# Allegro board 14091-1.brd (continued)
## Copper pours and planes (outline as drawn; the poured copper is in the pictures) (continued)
0D95V_VGA_S0 on TOP: 81.44,103.25 81.31,103.38 81.31,103.63 81.19,103.76 79.54,103.76 79.28,104.01 79.28,104.65 79.03,104.9 78.65,104.9 78.52,105.03 78.52,107.7 78.65,107.82 79.28,107.82 79.66,107.44 79.66,106.55 79.92,106.3 80.68,106.3 80.81,106.17 80.81,104.9 80.93,104.78 84.62,104.78 84.74,104.65 84.74,104.01 84.62,103.89 84.11,103.89 83.47,103.25 83.22,103.25 82.71,103.76 81.95,103.76 81.82,103.63 81.82,103.38 81.69,103.25
0D95V_VGA_S0 on TOP: 100.62,103.25 99.98,103.89 99.98,106.55 100.24,106.81 102.27,106.81 102.4,106.68 102.4,103.38 102.27,103.25
0D95V_VGA_S0 on BOTTOM: 81.59,103.1 81.46,103.23 81.46,103.74 81.34,103.87 80.57,103.87 80.19,104.25 80.19,106.41 80.07,106.53 79.3,106.53 78.92,106.91 78.92,107.29 79.56,107.93 80.45,107.93 80.57,107.8 80.57,107.17 80.7,107.04 81.08,107.04 81.21,106.91 81.21,105.52 81.59,105.14 84.56,105.14 84.69,105.26 85.12,105.26 86.67,106.81 87.92,106.81 88.68,106.05 100.62,106.05 100.74,105.92 100.74,104.25 100.49,103.99 89.72,103.99 89.23,103.5 87.41,103.5 87.13,103.23 84.38,103.23 84.26,103.36 82.48,103.36 82.23,103.1 ; 8 cut-outs
1D0V_S5 on TOP: 37.75,138.68 37.75,140.46 39.02,140.46 39.15,140.59 39.15,141.6 40.29,142.75 40.29,143.13 40.8,143.64 41.82,143.64 41.94,143.51 43.26,143.51 45.5,145.75 45.5,155.7 45.75,155.96 49.82,155.96 50.45,155.32 50.45,153.92 50.58,153.8 57.92,153.8 59.47,152.25 59.47,141.73 59.34,141.6 57.44,141.6 57.31,141.73 57.31,141.86 57.18,141.99 55.28,141.99 55.15,141.86 55.15,141.35 54.9,141.1 53.75,141.1 53.63,141.22 53.63,141.6 53.37,141.86 52.23,141.86 50.96,140.59 48.42,140.59 48.29,140.72 48.29,142.24 48.42,142.37 49.82,142.37 49.82,144.4 49.56,144.65 48.17,144.65 46.77,143.26 46.77,141.73 46.64,141.6 41.69,141.6 40.93,140.84 40.93,138.81 40.8,138.68 ; 6 cut-outs
1D8V_S0 on BOTTOM: 81.31,196.98 81.06,197.23 81.06,197.61 80.68,197.99 79.54,197.99 79.28,198.25 79.28,199.14 79.41,199.26 82.71,199.26 82.84,199.14 82.84,198.75 83.85,197.74 83.85,197.1 83.73,196.98 ; 4 cut-outs
1D8V_S5 on TOP: 91.73,124.33 91.47,124.59 91.47,126.49 91.6,126.62 93,126.62 93.38,126.24 95.16,126.24 95.28,126.36 95.28,127.38 95.08,127.58 93.99,127.58 93.96,127.61 93.96,128.09 94.01,128.14 95.46,128.14 95.56,128.04 95.56,127.84 95.77,127.64 97.06,127.64 97.19,127.51 97.19,125.6 97.06,125.48 96.68,125.48 96.43,125.22 96.43,124.46 96.3,124.33 ; 5 cut-outs
1D8V_S5 on BOTTOM: 81.44,199.52 81.31,199.64 81.31,201.29 81.57,201.55 84.87,201.55 85.12,201.29 85.12,199.64 85,199.52
1D8V_VGA_S0 on TOP: 97.44,66.17 97.06,66.55 94.52,66.55 94.27,66.8 94.27,72.01 98.08,75.82 98.08,82.8 98.46,83.19 100.24,83.19 101,82.42 101,77.72 101.38,77.34 101.38,69.85 101.25,69.72 99.86,69.72 99.86,70.48 99.22,71.12 97.44,71.12 97.19,70.87 97.19,67.18 97.44,66.93 98.97,66.93 99.09,66.8 99.09,66.17
1D8V_VGA_S0 on TOP: 93.67,109.77 93.56,109.88 93.56,110.29 93.62,110.34 94.04,110.34 95.76,112.07 95.76,112.08 96.04,112.36 96.06,112.36 96.96,113.26 96.96,115.7 97.08,115.82 97.85,115.82 97.97,115.7 97.97,112.12 97.85,111.99 97.08,111.99 96.83,111.74 96.73,111.74 94.76,109.77 ; 3 cut-outs
1D35V_S3 on TOP: 156.37,150.88 155.86,151.38 155.86,166.12 156.12,166.37 158.53,166.37 158.78,166.62 158.78,167.26 158.91,167.39 159.42,167.39 159.42,151.51 158.78,150.88 ; 9 cut-outs
1D35V_S3 on TOP: 90.84,204.09 90.71,204.22 90.71,208.91 90.84,209.04 92.62,209.04 92.74,209.17 92.74,211.2 93.25,211.71 102.14,211.71 103.28,210.57 103.28,208.15 103.54,207.9 103.54,205.87 102.9,205.23 93,205.23 91.85,204.09 ; 1 cut-out
1D35V_S3 on TOP: 140.75,152.02 140.62,152.15 140.62,166.24 140.88,166.5 144.69,166.5 144.94,166.24 144.94,152.4 144.56,152.02 143.16,152.02 143.04,152.15 143.04,152.65 142.78,152.91 141.77,152.91 141.51,152.65 141.51,152.15 141.38,152.02
1D35V_S3 on TOP: 127.92,151.38 127.67,151.64 127.67,168.53 127.92,168.78 129.95,168.78 130.08,168.66 130.08,168.15 129.83,167.89 129.83,151.64 129.57,151.38
1D35V_S3 on BOTTOM: outline of 92 points within 90.33,150.88 159.16,211.71 ; 97 cut-outs
1D35V_VGA_S0 on TOP: 91.73,66.04 90.08,67.69 81.95,67.69 81.44,68.2 81.44,71.88 81.38,71.95 81.38,73.34 78.14,76.58 76.49,76.58 75.47,77.6 75.47,80.01 75.73,80.26 79.15,80.26 83.22,76.2 85,76.2 85.12,76.07 85.12,74.3 85.38,74.04 85.38,71.12 85.5,70.99 89.06,70.99 89.19,70.87 90.97,70.87 91.09,70.74 91.09,69.34 92.24,68.2 93.89,68.2 94.01,68.07 94.01,66.17 93.89,66.04 ; 5 cut-outs
1D35V_VGA_S0 on TOP: 49.16,96.29 49.06,96.39 49.06,97.16 49.18,97.28 50.58,97.28 50.83,97.54 50.83,98.42 49.82,99.44 48.55,99.44 48.42,99.57 48.42,101.09 48.8,101.47 48.8,107.31 48.7,107.42 48.7,108.06 48.79,108.15 50.22,108.15 50.37,108 50.37,105.8 50.94,105.22 50.94,103.41 50.78,103.24 50.77,103.24 50.36,102.84 50.36,102.02 49.82,101.47 49.82,100.84 50.2,100.46 52.23,100.46 52.71,99.98 52.71,96.74 52.25,96.29 ; 11 cut-outs
1D35V_VGA_S0 on TOP: 48.9,114.17 48.59,114.47 48.59,118.36 49.23,119 52.48,119 52.74,118.75 52.74,118.49 52.48,118.24 52.48,117.35 52.61,117.22 53.12,117.22 53.37,116.97 53.37,116.71 53.12,116.46 53.12,115.7 53.39,115.43 53.39,115.3 52.76,114.68 50.88,114.68 50.37,114.17 ; 6 cut-outs
1D35V_VGA_S0 on BOTTOM: 48.65,113.16 48.57,113.23 48.57,118.34 48.84,118.61 50.42,118.61 50.55,118.49 50.55,113.46 50.25,113.16 ; 5 cut-outs
1D35V_VGA_S0 on BOTTOM: 60.51,89.26 60.51,91.29 61.78,92.56 61.78,96.88 61.91,97.01 62.29,97.01 62.54,97.26 62.54,99.29 61.52,100.31 61.52,103.48 58.73,106.28 58.73,108.18 58.86,108.31 59.24,108.31 61.4,106.15 61.4,106.02 62.92,104.5 63.56,104.5 64.19,103.87 64.19,103.1 65.08,102.21 66.48,102.21 67.49,101.2 71.94,101.2 72.19,101.45 72.19,103.76 72.6,104.17 76.05,104.17 76.51,104.63 76.51,105.9 76.64,106.02 77.91,106.02 78.16,106.28 78.92,106.28 79.05,106.15 79.05,103.99 78.67,103.61 78.67,97.39 78.8,97.26 78.8,93.71 78.42,93.32 77.78,93.32 77.02,92.56 72.95,92.56 71.56,93.96 65.72,93.96 61.02,89.26 ; 14 cut-outs
1D35V_VGA_S0 on BOTTOM: 48.55,82.3 48.42,82.42 48.42,86.36 48.59,86.53 48.59,90.04 48.95,90.4 48.95,90.82 49.13,91 50.22,91 50.37,91.16 52.17,91.16 52.66,90.67 52.66,89.55 52.17,89.07 51.64,89.07 51.46,88.89 51.46,88.21 51.87,87.8 52.48,87.8 52.86,88.18 53.29,88.18 53.44,88.03 53.44,86.38 53.29,86.23 53.09,86.23 52.58,86.74 51.92,86.74 51.64,86.46 51.64,85.85 51.87,85.62 52.12,85.62 52.3,85.8 52.66,85.8 52.73,85.72 52.73,84.6 52.75,84.59 52.75,83.07 51.98,82.3 ; 9 cut-outs
1D35V_VGA_S0 on BOTTOM: 52,94.97 50.57,96.39 48.77,96.39 48.59,96.57 48.59,99.23 48.77,99.41 50.5,99.41 50.68,99.59 50.68,100.12 48.85,101.95 48.85,105.86 49.05,106.06 50.8,106.06 51.18,105.68 51.18,101.65 52.61,100.22 52.61,95.17 52.4,94.97 ; 1 cut-out
1D35V_VGA_S0 on L3: 48.04,99.31 48.17,99.44 48.17,118.62 48.8,119.25 52.99,119.25 53.25,119 53.25,115.57 52.23,114.55 52.23,112.14 52.1,112.01 51.47,112.01 50.83,112.65 50.33,112.65 49.94,112.27 49.94,108.46 50.33,108.08 50.96,108.08 51.34,108.46 51.72,108.46 51.85,108.33 51.85,107.31 52.1,107.06 52.1,106.68 51.21,105.79 51.21,102.36 51.98,101.6 51.98,96.9 50.58,95.5 50.58,95.12 49.94,94.49 49.94,91.57 50.33,91.19 50.96,91.19 51.21,90.93 51.21,90.04 51.47,89.79 51.49,89.79 52.38,88.9 52.38,88.23 52.89,87.73 52.89,85.31 53.39,84.81 55.55,84.81 57.08,86.33 57.71,86.33 58.35,85.69 58.35,84.43 57.7,83.79 52.52,83.79 52.48,83.82 51.85,83.82 48.04,87.63
1D35V_VGA_S0 on L4: 52.68,123.38 65.76,123.38 69.12,120.02 71.28,120.02 74.71,116.59 76.11,116.59 79.43,113.26 79.43,106.41 79.43,106.4 79.43,101.98 79.41,101.96 79.41,98.68 84.62,93.47 84.62,92.08 86.14,90.55 86.14,90.42 86.16,90.4 86.16,89.05 86.14,89.03 86.14,83.69 86.01,83.57 80.3,83.57 78.49,81.76 78.49,78.97 78.27,78.74 75.52,78.74 75.14,79.12 75.14,79.58 74.28,80.44 70.34,80.44 69.5,81.28 53.25,81.28 47.88,86.65 47.88,118.58 ; 1 cut-out
3D3V_RUN_FFS on TOP: 82.96,63.88 82.84,64.01 82.84,66.8 83.09,67.06 83.6,67.06 83.85,66.8 83.85,65.91 84.11,65.66 85.12,65.66 85.12,64.77 84.62,64.77 83.73,63.88 ; 2 cut-outs
62883AGND on TOP: 128.3,98.55 128.3,102.11 131.86,102.11 131.86,98.55
62883AGND on BOTTOM: 128.3,98.55 128.3,100.84 128.18,100.97 128.05,100.97 127.92,101.09 127.92,102.49 128.05,102.62 131.48,102.62 131.99,103.12 133.13,103.12 133.26,103 133.26,102.62 133.13,102.49 132.37,102.49 132.11,102.23 132.11,98.81 131.86,98.55 ; 6 cut-outs
AD+_TO_SYS on TOP: 63.91,38.35 63.79,38.48 63.79,40.89 63.41,41.27 62.64,41.27 62.39,41.53 62.39,42.67 71.15,42.67 71.41,42.42 71.41,38.35
AD+_TO_SYS on BOTTOM: 67.47,38.35 66.84,38.99 61.37,38.99 61.37,42.29 61.76,42.67 71.15,42.67 71.41,42.42 71.41,38.35
AD_JK on TOP: 59.6,23.5 57.44,25.65 56.17,25.65 55.79,25.27 54.26,25.27 53.5,26.04 53.5,27.81 53.88,28.19 54.9,28.19 55.53,28.83 55.53,30.1 56.68,31.24 56.68,38.73 56.8,38.86 61.5,38.86 62.01,38.35 62.01,31.37 62.52,30.86 68.61,30.86 68.74,30.73 68.74,28.83 68.61,28.7 66.07,28.7 65.82,28.45 65.82,26.67 64.68,25.53 64.68,23.88 64.3,23.5 ; 2 cut-outs
AD_JK on BOTTOM: 60.23,22.86 57.44,25.65 56.17,25.65 55.79,25.27 54.26,25.27 53.5,26.04 53.5,27.81 53.88,28.19 54.9,28.19 55.53,28.83 55.53,30.1 56.8,31.37 68.11,31.37 68.36,31.11 68.36,28.45 67.6,27.69 66.71,27.69 64.17,25.15 64.17,23.11 63.91,22.86 ; 4 cut-outs
AD_JK on L3: 55.79,25.27 56.17,25.65 57.44,25.65 58.83,24.26 60.36,24.26 64.8,28.7 68.61,28.7 68.74,28.83 68.74,30.61 68.49,30.86 62.64,30.86 62.26,30.48 57.18,30.48 54.9,28.19 53.88,28.19 53.5,27.81 53.5,26.04 54.26,25.27
BT+ on TOP: 39.02,66.04 39.02,67.31 38.9,67.44 30.77,67.44 30.64,67.56 30.64,74.3 30.89,74.55 33.43,74.55 33.56,74.42 33.56,72.9 33.94,72.52 42.71,72.52 43.09,72.14 43.09,66.17 42.96,66.04 ; 5 cut-outs
CAGND on TOP: 38.72,23.16 38.64,23.24 38.64,24.77 38.51,24.89 34.83,24.89 34.7,25.02 34.7,26.67 33.94,27.43 33.94,28.07 34.2,28.32 37.5,28.32 38.01,28.83 39.02,28.83 39.28,28.57 39.28,23.24 39.2,23.16 ; 10 cut-outs
CHG_AGND on TOP: 40.42,43.18 40.17,43.43 40.17,45.09 40.29,45.21 40.8,45.21 40.93,45.09 40.93,44.32 41.31,43.94 43.21,43.94 43.85,44.58 43.85,46.61 45.75,46.61 45.88,46.74 45.88,47.12 46.01,47.24 46.64,47.24 46.77,47.12 46.77,43.69 46.64,43.56 43.21,43.56 42.83,43.18 ; 8 cut-outs
DC_19V on TOP: 62.64,31.75 62.39,32 62.39,36.96 63.03,37.59 71.28,37.59 71.41,37.47 71.41,36.45 71.28,36.32 69.88,36.32 69.5,35.94 69.5,31.88 69.38,31.75 ; 4 cut-outs
DC_19V on BOTTOM: 62.77,34.29 62.39,34.67 62.39,35.18 61.37,36.2 61.37,38.23 66.58,38.23 67.22,37.59 71.03,37.59 71.28,37.34 71.28,35.05 70.52,34.29
DCBATOUT on TOP: 20.1,165.61 19.97,165.74 19.97,172.09 20.23,172.34 26.83,172.34 27.34,171.83 27.34,165.86 27.08,165.61
DCBATOUT on TOP: 40.04,72.9 39.78,73.15 39.78,74.93 39.53,75.18 39.53,75.69 39.28,75.95 39.28,76.83 39.53,77.09 41.94,77.09 43.09,75.95 43.09,73.03 42.96,72.9
DCBATOUT on TOP: 106.71,61.85 106.21,62.36 106.21,67.31 106.59,67.69 121.95,67.69 122.59,68.33 123.6,68.33 126.4,71.12 126.4,74.68 126.78,75.06 126.78,83.06 132.24,83.06 132.43,82.87 132.43,81.85 132.62,81.66 138.08,81.66 138.08,78.36 137.83,78.11 136.94,78.11 136.56,77.72 136.56,75.06 133.76,72.26 133.38,72.26 132.88,71.75 132.88,71.37 126.46,64.96 125.83,64.96 124.11,63.25 112.43,63.25 111.03,61.85
DCBATOUT on TOP: 67.22,43.05 66.96,43.31 61.76,43.31 61.63,43.43 61.63,44.45 61.12,44.96 51.98,44.96 46.9,50.04 41.31,50.04 41.18,50.16 41.18,54.23 41.31,54.36 49.69,54.36 54.01,50.04 63.28,50.04 65.06,48.26 74.33,48.26 74.84,48.77 74.84,49.4 74.96,49.53 75.22,49.53 75.34,49.4 75.34,48.9 75.73,48.51 94.39,48.51 94.71,48.2 97.38,48.2 98.46,47.12 98.46,45.85 96.11,43.5 85.19,43.5 84.87,43.81 72.68,43.81 71.92,43.05
DCBATOUT on TOP: 34.32,79.12 33.94,79.5 33.94,81.92 29.88,85.98 29.88,132.46 27.97,134.37 16.04,134.37 15.78,134.62 15.78,138.56 16.04,138.81 24.67,138.81 25.31,139.45 25.31,140.84 25.5,141.03 32.74,141.03 33.12,140.65 33.12,136.59 35.09,134.62 35.09,89.41 39.28,85.22 39.28,79.38 39.02,79.12 ; 4 cut-outs
DCBATOUT on TOP: 150.78,45.09 150.66,45.21 150.66,47.12 150.78,47.24 151.67,47.24 151.8,47.12 151.8,45.34 151.54,45.09
DCBATOUT on TOP: 46.01,37.08 45.88,37.21 45.88,40.39 46.01,40.51 47.02,40.51 47.28,40.77 52.74,40.77 52.99,40.51 52.99,39.5 52.87,39.37 49.18,39.37 48.93,39.12 48.93,38.61 48.8,38.48 47.91,38.48 47.53,38.1 47.53,37.21 47.4,37.08 ; 1 cut-out
DCBATOUT on BOTTOM: 127.03,75.44 126.78,75.69 126.78,83.06 132.24,83.06 132.37,82.93 132.37,81.92 132.62,81.66 138.08,81.66 138.08,78.36 137.83,78.11 136.94,78.11 136.56,77.72 136.56,75.56 136.43,75.44 ; 2 cut-outs
DCBATOUT on BOTTOM: 14.64,136.14 14,136.78 14,149.48 12.99,150.5 12.99,168.91 14.77,170.69 14.77,186.82 14.38,187.2 14.38,201.8 14.77,202.18 14.77,206.38 15.02,206.63 15.02,211.23 17.31,213.51 17.31,218.57 20.48,221.74 33.69,221.74 35.47,223.52 56.04,223.52 56.55,223.01 59.98,223.01 60.23,222.76 60.23,221.23 60.1,221.11 55.41,221.11 55.02,221.49 36.48,221.49 34.7,219.71 21.62,219.71 19.46,217.55 19.46,216.41 20.1,215.77 25.18,215.77 25.69,216.28 26.96,216.28 27.21,216.53 34.96,216.53 35.21,216.28 35.21,213.23 35.09,213.11 33.94,213.11 32.93,214.12 26.07,214.12 25.56,213.61 21.14,213.61 17.57,210.05 17.57,209.64 17.56,209.63 17.56,188.85 18.07,188.34 25.69,188.34 28.1,190.75 33.18,190.75 34.45,192.02 45.88,192.02 46.01,191.9 46.01,189.74 45.75,189.48 41.69,189.48 39.15,186.94 28.48,186.94 26.7,185.17 18.7,185.17 18.45,184.91 18.45,172.85 18.96,172.34 26.83,172.34 27.34,171.83 27.34,165.86 27.08,165.61 21.37,165.61 19.59,163.83 19.59,136.27 19.46,136.14
DCBATOUT on BOTTOM: 78.14,218.95 77.5,219.58 77.5,223.9 78.01,224.41 81.69,224.41 81.82,224.28 81.82,219.2 81.57,218.95
DCBATOUT on BOTTOM: 63.66,45.09 62.39,46.35 57.44,46.35 56.42,47.37 52.74,47.37 48.67,51.44 45.25,51.44 44.86,51.05 44.86,50.29 44.48,49.91 41.31,49.91 41.18,50.04 41.18,56.26 41.31,56.39 44.99,56.39 45.25,56.64 45.25,72.14 44.36,73.03 40.04,73.03 39.78,73.28 39.78,74.93 39.53,75.18 39.53,75.56 39.09,76.01 39.02,76.01 35.21,79.82 35.21,81.79 35.47,82.04 43.21,82.04 50.58,74.68 50.58,53.09 54.33,49.34 56.99,49.34 58.07,48.26 64.55,48.26 65.31,47.5 65.31,45.21 65.18,45.09 ; 3 cut-outs
DCBATOUT on BOTTOM: 121.95,23.11 121.32,23.75 108.75,23.75 106.08,26.42 106.08,28.19 102.9,31.37 102.9,42.8 100.24,45.47 95.03,45.47 94.65,45.85 94.65,50.55 96.3,52.2 96.3,60.07 101.38,65.15 109.38,65.15 109.89,64.64 109.89,62.23 109.51,61.85 106.08,61.85 101.63,57.4 101.63,50.8 110.36,42.08 110.36,29.76 111.67,28.45 120.05,28.45 120.81,29.21 129.7,29.21 130.72,30.23 141,30.23 143.16,32.38 149,32.38 149.26,32.13 149.26,30.23 149.13,30.1 143.8,30.1 141.89,28.19 132.88,28.19 130.97,26.29 124.75,26.29 124.62,26.16 124.62,23.5 124.24,23.11
DCBATOUT on L3: 77,223.39 78.39,222 78.39,219.84 78.01,219.46 77.5,219.46 75.6,221.36 60.36,221.36 60.1,221.11 58.33,221.11 58.2,221.23 58.2,223.01 58.58,223.39
DCBATOUT_VCCGTA on TOP: 36.99,209.04 36.74,209.3 36.74,215.01 39.78,218.06 47.53,218.06 47.53,212.6 47.28,212.34 41.56,212.34 38.9,209.68 38.9,209.3 38.64,209.04
DCBATOUT_VCCGTA on BOTTOM: 35.97,212.22 35.72,212.47 35.72,216.79 35.34,217.17 27.72,217.17 27.72,219.33 27.85,219.46 37.88,219.46 38.39,218.95 41.82,218.95 41.82,214.88 41.05,214.12 41.05,212.47 40.8,212.22
DCBATOUT_VCCGTB on TOP: 34.58,192.41 34.45,192.53 34.45,197.74 34.58,197.87 41.94,197.87 42.32,198.25 47.53,198.25 47.66,198.12 47.66,192.53 47.53,192.41
DCBATOUT_VCCGTB on BOTTOM: 34.58,192.41 34.32,192.66 34.32,197.74 34.45,197.87 41.44,197.87 43.34,195.96 45.88,195.96 46.13,195.71 46.13,192.66 45.88,192.41
DCBATOUT_VCCSA on TOP, BOTTOM: 32.16,164.47 32.04,164.59 32.04,164.97 31.28,165.74 29.5,165.74 29.24,165.99 28.1,165.99 27.97,166.12 27.97,171.45 28.1,171.58 34.58,171.58 34.83,171.32 34.83,164.47
DCBATOUT_VCORE on TOP: 19.34,172.97 19.21,173.1 19.21,178.44 19.46,178.69 33.05,178.69 33.05,173.23 32.8,172.97
DCBATOUT_VCORE on BOTTOM: 19.34,172.97 19.21,173.1 19.21,177.8 26.58,177.8 27.47,178.69 33.05,178.69 33.05,173.23 32.8,172.97
ISW_1 on BOTTOM: 41.05,34.42 40.8,34.67 40.8,38.61 40.81,38.62 40.81,39.05 41,39.24 44.1,39.24 44.61,38.73 44.61,34.8 44.48,34.67 42.96,34.67 42.71,34.42
LX on TOP: 33.43,31.24 33.31,31.37 33.31,38.1 38.26,38.1 38.64,37.72 38.64,31.62 38.26,31.24
LX on BOTTOM: 33.48,30.28 32.8,30.96 32.8,34.67 32.93,34.8 35.34,34.8 35.47,34.92 35.47,37.47 36.23,38.23 36.23,39.88 37.37,39.88 37.5,39.75 37.5,38.23 37.63,38.1 38.26,38.1 38.64,37.72 38.64,32.51 38.51,32.38 35.72,32.38 35.54,32.21 35.54,30.4 35.42,30.28
MCT_R on TOP: 60.23,9.65 60.1,9.78 60.1,14.1 60.23,14.22 62.52,14.22 62.77,13.97 63.53,13.97 63.79,14.22 63.79,16.89 66.2,16.89 66.2,13.92 65.06,12.78 65.06,10.54 64.42,9.91 62.77,9.91 62.52,9.65 ; 2 cut-outs
P1P2V on BOTTOM: 64.42,58.55 63.41,59.56 58.71,59.56 57.95,60.33 53.88,60.33 53.75,60.45 53.75,62.36 53.93,62.53 54.59,62.53 55.53,61.59 57.95,61.59 58.58,60.96 63.28,60.96 64.42,62.1 66.2,62.1 66.2,58.55 ; 3 cut-outs
P3P3V on BOTTOM: 58.48,61.98 58.4,62.05 58.4,63.63 58.15,63.88 56.17,63.88 56.04,64.01 56.04,65.15 55.66,65.53 55.28,65.53 55.15,65.66 55.15,66.55 55.91,66.55 56.17,66.29 57.95,66.29 58.07,66.17 58.07,65.79 58.2,65.66 61.37,65.66 61.63,65.41 61.63,62.36 61.25,61.98 ; 3 cut-outs
PWR_0D95V_VGA_LX on TOP: 106.97,103.63 106.97,105.92 110.14,105.92 110.27,105.79 110.27,104.27 109,104.27 108.36,103.63
PWR_0D95V_VGA_PVIN on TOP: 115.22,104.01 115.1,104.14 115.1,104.78 114.97,104.9 113.32,104.9 113.19,104.78 112.81,104.78 112.68,104.9 112.68,106.05 112.3,106.43 112.3,108.84 112.43,108.97 115.98,108.97 116.11,108.84 116.11,104.14 115.98,104.01 ; 4 cut-outs
PWR_1D0V_PHASE on TOP: 37.75,144.4 37.63,144.53 37.63,148.59 37.5,148.72 36.23,148.72 36.1,148.84 36.1,151 35.97,151.13 35.47,151.13 35.34,151.26 35.34,156.72 35.47,156.84 42.58,156.84 42.83,156.59 42.83,147.07 42.71,146.94 41.56,146.94 41.44,146.81 41.44,144.53 41.31,144.4
PWR_1D0V_PHASE on BOTTOM: 37.75,144.4 37.63,144.53 37.63,148.59 37.5,148.72 36.23,148.72 36.1,148.84 36.1,151 35.97,151.13 33.94,151.13 33.82,151.26 33.82,156.72 33.94,156.84 42.58,156.84 42.83,156.59 42.83,147.07 42.71,146.94 41.56,146.94 41.44,146.81 41.44,144.53 41.31,144.4
PWR_1D8V on TOP: 104.68,72.9 104.68,73.28 103.54,73.28 103.54,73.41 103.28,73.66 101.89,73.66 101.76,73.79 101.76,79.12 101.89,79.25 103.54,79.25 103.79,78.99 103.79,78.36 104.3,77.85 107.98,77.85 108.36,78.23 110.78,78.23 110.9,78.11 110.9,73.66 110.14,72.9 ; 9 cut-outs
PWR_1D8V_LX on TOP: 114.08,72.9 113.83,73.15 113.83,78.11 113.95,78.23 117.58,78.23 117.79,78.03 117.79,77.57 118.02,77.34 118.02,75.69 118.14,75.56 119.79,75.56 119.79,74.55 119.67,74.42 118.52,74.42 117,72.9 ; 1 cut-out
PWR_3D3V_LGATE2 on BOTTOM: 135.54,21.21 135.54,22.23 136.94,22.23 137.07,22.1 137.07,21.34 136.94,21.21
PWR_3D3V_PHASE2 on TOP: 130.34,15.88 130.08,16.13 130.08,20.45 130.34,20.7 136.05,20.7 136.43,20.32 136.43,16 136.3,15.88
PWR_3D3V_PHASE2 on BOTTOM: 137.19,14.35 135.67,15.88 129.95,15.88 129.83,16 129.83,18.92 133,18.92 133.13,19.05 133.13,20.7 136.05,20.7 136.43,20.32 136.43,16.51 137.19,15.75 138.59,15.75 138.72,15.62 138.72,14.48 138.59,14.35
PWR_3D3V_UGATE2 on BOTTOM: 128.68,16.89 128.56,17.02 128.56,18.8 128.68,18.92 129.57,18.92 129.57,17.02 129.45,16.89
PWR_5V_LGATE1 on BOTTOM: 141.89,21.21 141.89,22.23 143.16,22.23 143.29,22.1 143.29,21.34 143.16,21.21
PWR_5V_PHASE1 on TOP: 137.19,14.35 137.07,14.48 137.07,15.62 137.19,15.75 138.59,15.75 139.48,16.64 139.48,20.57 139.61,20.7 146.46,20.7 146.72,20.45 146.72,16.26 146.34,15.88 140.24,15.88 138.72,14.35
PWR_5V_PHASE1 on BOTTOM: 140.24,15.88 139.48,16.64 139.48,20.45 139.61,20.57 142.78,20.57 142.91,20.45 142.91,17.02 143.42,16.51 144.94,16.51 145.19,16.76 145.19,17.78 145.07,17.91 145.07,18.92 146.72,18.92 146.72,16.26 146.34,15.88
PWR_5V_UGATE1 on BOTTOM: 143.92,16.89 143.54,17.27 143.54,18.8 143.67,18.92 144.81,18.92 144.81,17.02 144.69,16.89
PWR_CHG_BT_LR on TOP: 37.75,60.45 37.29,60.91 37.29,61.44 35.62,63.12 35.62,63.65 35.82,63.86 38.74,63.86 38.9,64.01 38.9,65.28 39.02,65.41 42.96,65.41 43.09,65.28 43.09,63.75 43.21,63.63 43.85,63.63 43.98,63.5 43.98,60.58 43.85,60.45
PWR_CHG_PHASE on TOP: 37.12,55.12 36.99,55.24 36.99,59.18 37.24,59.44 43.59,59.44 43.72,59.31 43.72,55.24 43.59,55.12
PWR_CHG_PHASE on BOTTOM: 37.12,55.12 36.99,55.24 36.99,60.25 37.85,61.11 42.27,61.11 43.72,59.66 43.72,56.77 40.93,56.77 40.55,56.39 40.55,55.24 40.42,55.12
PWR_DCBATOUT_1D0V on TOP: 25.69,141.86 25.56,141.99 25.56,144.4 27.72,146.56 29.37,146.56 29.75,146.94 29.75,148.59 29.88,148.72 32.29,148.72 32.8,148.21 37.37,148.21 37.37,142.62 36.61,141.86
PWR_DCBATOUT_1D0V on BOTTOM: 25.69,141.86 25.56,141.99 25.56,144.4 27.72,146.56 27.72,149.86 31.15,149.86 32.8,148.21 37.37,148.21 37.37,142.62 36.61,141.86
PWR_DCBATOUT_1D8V on TOP: 124.49,69.95 124.12,70.32 124.12,72.38 123.99,72.52 122.08,72.52 121.83,72.77 121.83,74.17 121.7,74.3 120.18,74.3 120.18,74.55 121.95,74.55 122.21,74.8 122.21,75.44 122.33,75.56 123.99,75.56 124.62,74.93 125.64,74.93 125.64,70.46 125.13,69.95
PWR_DCBATOUT_3D3V on TOP: 128.18,22.61 127.92,22.86 127.92,27.3 128.18,27.56 132.11,27.56 132.37,27.3 132.37,22.73 132.24,22.61
PWR_DCBATOUT_3D3V on BOTTOM: 128.68,19.43 128.68,22.1 128.56,22.23 126.53,22.23 125,23.75 125,25.65 125.13,25.78 132.24,25.78 132.37,25.65 132.37,22.73 131.99,22.35 131.99,19.43 ; 2 cut-outs
PWR_DCBATOUT_5V on TOP: 142.53,22.61 142.4,22.73 142.4,27.3 142.65,27.56 145.96,27.56 146.21,27.3 146.21,23.88 146.46,23.62 146.46,22.86 146.21,22.61
PWR_DCBATOUT_5V on BOTTOM: 143.92,19.43 143.92,22.35 143.54,22.73 143.54,29.46 143.67,29.59 149,29.59 149.13,29.46 149.13,26.29 147.23,24.38 147.23,19.43 ; 2 cut-outs
PWR_DCBATOUT_VDDQ on TOP: 85.5,216.92 85.12,217.3 85.12,219.58 84.11,220.6 84.11,221.87 84.36,222.12 84.36,223.65 89.57,223.65 89.82,223.39 89.82,217.17 89.57,216.92
PWR_DCBATOUT_VDDQ on BOTTOM: 82.58,219.07 82.33,219.33 82.33,224.54 89.44,224.54 90.2,225.3 95.66,225.3 95.92,225.04 95.92,219.96 95.79,219.84 84.49,219.84 83.73,219.07 ; 2 cut-outs
PWR_VCCGT_SWA on TOP: 44.1,205.87 44.1,211.46 47.66,211.46 47.91,211.71 47.91,216.28 54.01,216.28 54.26,216.03 54.26,206.25 53.88,205.87
PWR_VCCGT_SWA on BOTTOM: 44.1,205.87 44.1,211.46 45.75,211.46 46.01,211.71 46.01,214.38 47.91,216.28 54.01,216.28 54.26,216.03 54.26,206.25 53.88,205.87
PWR_VCCGT_SWB on TOP: 47.91,192.66 47.91,196.47 49.69,196.47 49.82,196.6 49.82,197.99 49.44,198.37 49.44,199.01 49.18,199.26 44.23,199.26 44.1,199.39 44.1,204.85 54.14,204.85 54.26,204.72 54.26,192.91 54.01,192.66
PWR_VCCGT_SWB on BOTTOM: 48.17,192.66 47.91,192.91 47.91,195.45 46.52,196.85 46.52,199.14 46.39,199.26 44.23,199.26 44.1,199.39 44.1,204.85 54.14,204.85 54.26,204.72 54.26,192.91 54.01,192.66
PWR_VCCSA_PH on TOP: 33.69,159.89 33.56,160.02 33.56,163.32 35.21,163.32 35.34,163.45 35.34,166.62 36.36,166.62 36.61,166.37 37.37,166.37 37.63,166.62 37.63,166.88 37.75,167 39.4,167 39.53,166.88 39.53,160.02 39.4,159.89
PWR_VCORE_SW on TOP: 33.43,173.61 33.31,173.74 33.31,176.91 35.09,176.91 35.21,177.04 35.21,179.58 35.09,179.71 29.5,179.71 29.5,187.58 29.62,187.71 30.64,187.71 30.77,187.58 30.77,185.42 30.89,185.29 38.64,185.29 39.02,184.91 39.02,175.26 38.64,174.88 35.34,174.88 35.09,174.62 35.09,173.74 34.96,173.61
PWR_VCORE_SW on BOTTOM: 33.31,174.88 33.31,178.18 35.09,178.18 35.21,178.31 35.21,179.58 35.09,179.71 29.5,179.71 29.5,185.17 29.62,185.29 38.64,185.29 39.02,184.91 39.02,175.26 38.64,174.88
PWR_VDDQ_PHASE on TOP: 92.62,215.65 92.36,215.9 92.36,220.6 92.87,221.11 102.78,221.11 103.41,220.47 103.41,215.9 103.16,215.65
PWR_VDDQ_PHASE on BOTTOM: 92.62,215.65 91.98,216.28 91.98,219.58 96.05,219.58 96.43,219.96 96.43,220.73 96.81,221.11 98.46,221.11 98.84,221.49 98.84,223.14 98.97,223.27 104.3,223.27 104.49,223.08 104.49,216.98 103.16,215.65
PWR_VDDQ_VLDOIN on TOP: 88.81,205.49 88.68,205.61 88.68,209.3 87.66,210.31 87.66,210.82 87.79,210.95 90.2,210.95 90.46,210.69 90.46,209.55 90.2,209.3 90.2,205.61 90.08,205.49
PWR_VGA_CORE_PHASE1 on TOP: 123.99,79.25 123.6,79.63 123.6,81.03 123.48,81.15 120.81,81.15 120.68,81.28 120.68,91.44 120.94,91.69 130.21,91.69 130.34,91.57 130.34,86.11 126.91,86.11 126.53,85.72 126.53,79.38 126.4,79.25
PWR_VGA_CORE_PHASE1 on BOTTOM: 125,77.98 125,79.12 124.87,79.25 123.99,79.25 123.6,79.63 123.6,81.03 123.48,81.15 120.81,81.15 120.68,81.28 120.68,91.44 120.94,91.69 130.21,91.69 130.34,91.57 130.34,86.11 126.91,86.11 126.53,85.72 126.53,77.98
RING2 on TOP: 169.32,75.44 168.82,75.95 168.13,75.95 168.05,76.02 168.05,76.53 168.13,76.61 169.17,76.61 169.58,76.2 172.12,76.2 172.25,76.07 172.25,75.56 172.12,75.44
SB3V on TOP: 66.71,190.5 66.58,190.63 66.58,192.28 66.71,192.41 68.74,192.41 69.76,191.39 69.76,190.88 69.63,190.75 68.11,190.75 67.85,190.5 ; 1 cut-out
SB3V on TOP: 88.3,122.56 88.3,125.73 88.17,125.86 86.39,125.86 86.27,125.98 86.27,128.14 86.65,128.52 90.97,128.52 91.35,128.14 93.43,128.14 93.53,128.04 93.53,127.66 93.89,127.3 94.93,127.3 95.05,127.18 95.05,126.75 94.93,126.62 93.56,126.62 93.17,127 91.22,127 91.09,126.87 91.09,122.68 90.97,122.56 ; 2 cut-outs
SB3V on TOP: 117.13,104.27 116.87,104.52 116.87,108.58 115.1,110.36 115.1,110.87 115.35,111.12 115.6,111.12 116.87,109.86 124.37,109.86 125.26,110.74 132.88,110.74 135.54,108.08 137.7,108.08 138.97,106.81 138.97,105.41 138.72,105.16 137.96,105.16 137.7,105.41 137.7,106.3 137.07,106.93 135.03,106.93 132.37,109.6 125.64,109.6 124.49,108.46 121.95,108.46 121.06,107.57 119.92,107.57 119.41,107.06 119.41,105.16 119.29,105.03 118.52,105.03 117.76,104.27 ; 2 cut-outs
SB3V on TOP: 81.44,139.32 80.68,140.08 80.68,140.84 82.84,140.84 82.96,140.72 82.96,139.95 82.33,139.32
SB3V on TOP: 156.24,187.45 155.86,187.83 155.86,190.37 155.48,190.75 154.72,190.75 148.88,196.6 148.88,203.07 147.99,203.96 147.99,206.25 149.51,207.77 158.15,207.77 161.2,204.72 165.39,204.72 165.77,204.34 165.77,201.55 165.39,201.17 156.75,201.17 154.72,203.2 151.93,203.2 151.54,202.82 151.54,199.39 157.26,193.68 157.26,192.28 158.66,190.88 159.8,190.88 159.93,190.75 159.93,187.71 159.67,187.45 ; 1 cut-out
SB3V on BOTTOM: 148.12,9.27 148.12,11.3 148.37,11.56 148.37,13.34 153.51,18.48 153.51,18.86 154.72,20.07 155.23,20.07 156.12,20.95 156.12,23.11 155.74,23.5 155.74,24.64 155.1,25.27 155.1,27.3 156.12,28.32 159.16,28.32 160.56,26.92 160.56,23.75 159.55,22.73 159.55,21.46 155.1,17.02 154.34,17.02 151.29,13.97 151.29,9.78 151.16,9.65 150.66,9.65 150.27,9.27 ; 1 cut-out
SB3V on BOTTOM: 50.71,5.46 50.07,6.1 49.56,6.1 49.44,6.22 49.44,7.37 49.56,7.49 50.45,7.49 50.58,7.37 50.58,6.86 51.34,6.1 51.34,5.84 50.96,5.46 ; 1 cut-out
SB3V on BOTTOM: 146.72,201.93 146.59,202.06 146.59,206.38 146.97,206.76 146.97,207.26 147.1,207.39 150.66,207.39 150.91,207.14 150.91,202.18 150.66,201.93 ; 6 cut-outs
SB3V on BOTTOM: 41.18,4.45 40.29,5.33 40.29,5.84 40.04,6.1 39.4,6.1 39.28,6.22 39.28,10.54 40.55,10.54 40.55,7.62 41.94,6.22 41.94,5.33 42.32,4.95 42.32,4.57 42.2,4.45 ; 2 cut-outs
SB3V on BOTTOM: 128.81,49.66 128.81,50.8 129.19,51.18 129.19,54.99 129.32,55.12 130.59,55.12 130.97,55.5 130.97,56.9 131.1,57.02 131.99,57.02 132.49,57.53 132.49,64.14 132.75,64.39 135.8,64.39 135.92,64.52 135.92,65.28 136.05,65.41 136.69,65.41 136.81,65.28 136.81,63.75 136.69,63.63 133.89,63.63 133.13,62.87 133.13,57.28 132.62,56.77 132.62,56.13 132.49,56.01 131.99,56.01 131.48,55.5 131.48,54.74 131.22,54.48 130.21,54.48 129.83,54.1 129.83,52.58 129.95,52.45 134.02,52.45 134.15,52.32 134.15,51.82 134.02,51.69 130.21,51.69 129.95,51.44 129.95,50.29 129.7,50.04 129.7,49.78 129.57,49.66 ; 4 cut-outs
SB3V on L4: 148.75,10.16 148.5,10.41 148.5,12.95 155.99,20.45 155.99,24.51 155.23,25.27 155.23,27.43 157.13,29.34 162.85,29.34 163.99,30.48 163.99,63.12 165.01,64.14 165.01,67.94 166.02,68.96 166.02,72.39 165.01,73.41 165.01,88.65 165.13,88.77 165.39,88.77 165.51,88.65 165.51,88.39 165.77,88.14 166.4,88.14 166.91,88.65 166.91,123.06 172.37,128.52 172.37,133.86 170.21,136.02 170.21,148.46 170.85,149.1 170.85,154.69 170.09,155.45 168.82,155.45 163.86,160.4 163.86,168.91 164.88,169.93 164.88,202.56 165.51,203.2 167.8,203.2 168.18,202.82 168.18,160.53 170.59,158.12 171.99,158.12 174.28,155.83 174.28,148.84 173.64,148.21 173.64,140.97 178.98,135.64 178.98,127.89 171.74,120.65 171.74,91.44 172.25,90.93 172.25,85.09 171.23,84.07 171.23,68.83 168.44,66.04 168.44,60.58 168.05,60.2 168.05,28.45 164.75,25.15 161.58,25.15 160.56,24.13 160.56,18.67 158.66,16.76 154.85,16.76 153.2,15.11 153.2,11.68 151.67,10.16
SB5V on TOP: 143.42,40.51 142.78,41.15 139.28,41.15 138.01,42.42 133.48,42.42 133.28,42.62 133.28,43.71 133.46,43.89 136,43.89 136.05,43.84 136.05,43.69 136.56,43.18 138.97,43.18 140.11,42.04 142.91,42.04 143.8,41.15 144.18,41.15 144.18,40.51
SB5V on BOTTOM: 148.24,4.32 148.12,4.45 148.12,7.87 150.15,7.87 150.53,7.49 151.16,7.49 151.29,7.37 151.29,6.73 150.4,5.84 150.4,4.45 150.27,4.32 ; 1 cut-out
SDREG2 on BOTTOM: 172.32,146.86 172.25,146.94 172.25,147.7 170.72,149.22 170.09,149.22 169.96,149.35 169.96,149.73 170.09,149.86 170.85,149.86 173.01,147.7 173.01,146.94 172.93,146.86
SIO_AGND on TOP: 138.08,43.69 137.96,43.81 137.96,44.45 136.94,45.47 136.56,45.47 136.43,45.59 136.43,46.74 137.62,47.93 138.26,47.93 138.31,47.88 138.31,47.75 137.45,46.89 137.45,45.72 137.96,45.21 138.46,45.21 138.59,45.09 138.59,44.32 138.72,44.2 138.72,43.81 138.59,43.69
SIO_AVCC3 on TOP: 149.26,45.34 148.88,45.72 147.48,45.72 147.23,45.97 147.23,46.1 145.07,48.26 142.91,48.26 142.91,49.66 143.04,49.78 143.42,49.78 144.05,49.15 145.96,49.15 146.97,48.13 147.99,48.13 148.12,48.01 148.12,47.12 148.24,46.99 149.89,46.99 150.02,46.86 150.02,45.47 149.89,45.34 ; 2 cut-outs
SLEEVE on TOP: 169.71,76.45 169.32,76.83 168.05,76.83 167.8,77.09 167.8,77.22 168.18,77.6 169.45,77.6 169.71,77.34 172.12,77.34 172.25,77.22 172.25,76.58 172.12,76.45 ; 1 cut-out
USBVCC01 on TOP: 163.23,119.63 163.1,119.76 163.1,122.68 165.77,125.35 171.48,125.35 173.13,123.7 173.13,120.02 172.75,119.63 ; 3 cut-outs
USBVCC23 on TOP: 90.58,4.19 90.46,4.32 90.46,12.57 90.97,13.08 90.97,20.07 91.09,20.19 92.49,20.19 93,20.7 93,40.26 94.52,41.78 101.89,41.78 102.01,41.66 102.01,39.5 101.51,38.99 96.17,38.99 95.16,37.97 95.16,19.56 95.92,18.8 101.51,18.8 101.89,18.41 101.89,16.64 101.51,16.26 95.16,16.26 94.65,15.75 94.65,11.94 92.87,10.16 92.87,4.45 92.62,4.19 ; 3 cut-outs
V_0P675_S3 on TOP: 126.53,125.73 126.02,126.24 126.02,127.51 126.14,127.64 127.03,127.64 127.41,127.25 129.32,127.25 129.57,127.51 129.57,127.76 129.7,127.89 130.08,127.89 130.34,127.64 131.22,127.64 131.48,127.38 131.48,126.36 130.84,125.73
V_0P675_S3 on BOTTOM: 104.68,193.04 99.47,198.25 95.03,198.25 91.85,201.42 91.22,201.42 91.09,201.55 91.09,208.91 91.22,209.04 92.24,209.04 92.36,208.91 92.36,202.56 95.66,199.26 100.11,199.26 105.44,193.93 105.44,193.17 105.32,193.04
V_0P675_S3 on BOTTOM: 129.57,125.73 129.45,125.86 129.45,126.36 129.57,126.49 129.57,127.76 129.7,127.89 129.95,127.89 130.72,127.13 137.07,127.13 137.19,127.25 137.19,127.64 137.45,127.89 138.08,127.89 138.21,127.76 138.21,127 138.46,126.75 144.18,126.75 144.56,127.13 144.56,127.51 144.69,127.64 145.32,127.64 145.45,127.51 145.45,126.75 145.58,126.62 147.99,126.62 149.64,128.27 154.72,128.27 155.23,127.76 155.23,125.86 155.1,125.73 151.54,125.73 150.91,126.36 148.75,126.36 148.12,125.73 136.43,125.73 135.8,126.36 133.38,126.36 132.75,125.73 ; 16 cut-outs
V_1P5_HDMI on TOP: 130.46,39.24 130.34,39.37 130.34,41.22 130.88,41.77 134.08,41.77 134.83,41.02 138.97,41.02 139.23,40.77 139.23,40.39 138.97,40.13 131.33,40.13 130.97,39.78 130.97,39.37 130.84,39.24 ; 1 cut-out
V_1P5_HDMI on BOTTOM: 137.29,30.43 137.02,30.71 137.02,31.95 137.27,32.21 138.21,32.21 138.46,32.46 138.46,34.8 137.96,35.31 137.96,38.35 138.63,39.03 138.65,39.03 138.67,39.04 138.67,40.72 138.84,40.89 140.37,40.89 140.62,40.64 141.77,40.64 141.89,40.51 141.89,40.13 141.77,40.01 140.24,40.01 139.96,39.73 139.96,38.71 139.86,38.61 139.86,34.92 139.48,34.92 139.48,30.56 139.35,30.43 ; 1 cut-out
V_1P05_LAN on TOP: 34.07,10.79 33.94,10.92 33.94,11.43 34.2,11.68 34.32,11.68 35.21,12.57 35.21,13.46 35.34,13.59 35.97,13.59 36.1,13.46 36.1,12.32 34.58,10.79 ; 1 cut-out
V_1P05_LAN on BOTTOM: 35.34,10.54 34.7,11.18 34.7,12.7 34.45,12.95 31.53,12.95 31.28,13.21 31.28,16 33.94,18.67 34.58,18.67 34.58,18.92 35.09,19.43 41.18,19.43 41.82,18.8 41.82,13.34 41.05,12.57 41.05,12.06 40.93,11.94 40.67,11.94 40.55,12.06 40.55,13.46 40.29,13.72 39.66,13.72 39.53,13.84 39.53,14.22 39.66,14.35 40.42,14.35 40.55,14.48 40.55,17.78 39.78,18.54 35.47,18.54 35.21,18.29 35.21,15.62 35.47,15.37 36.1,15.37 36.23,15.24 36.23,14.73 35.97,14.48 35.97,12.65 36.23,12.4 38.41,12.4 38.44,12.37 38.44,11.53 38.64,11.33 38.64,10.92 38.26,10.54 ; 6 cut-outs
V_1P05_LAN on L4: 37.75,17.4 41.82,17.4 41.94,17.27 41.94,14.1 40.93,13.08 36.74,13.08 35.21,11.56 35.21,11.05 36.36,9.91 37.37,9.91 37.75,10.29 37.75,10.92 38.39,11.56 38.77,11.56 38.9,11.43 38.9,9.91 37.63,8.64 35.59,8.64 33.31,10.92 33.31,13.72 34.45,14.86 35.21,14.86
V_3P3_A on TOP: 149.13,41.78 149,41.91 149,43.43 149.13,43.56 149.13,44.7 149.26,44.83 150.02,44.83 150.15,44.7 150.15,42.04 149.89,41.78
V_3P3_A on TOP: 130.84,7.11 129.95,8 127.8,8 127.8,8.64 127.92,8.76 128.3,8.76 128.46,8.92 128.46,10.95 129.83,12.32 129.83,14.73 130.21,15.11 135.54,15.11 135.8,14.86 135.8,11.43 135.16,10.79 135.16,7.37 134.91,7.11 ; 2 cut-outs
V_3P3_A on BOTTOM: 141.13,7.49 141.07,7.56 134.72,7.56 132.62,9.65 132.62,11.68 133,12.06 146.21,12.06 146.34,11.94 146.34,11.68 146.59,11.43 146.59,9.14 145.83,9.14 145.58,9.4 144.43,9.4 144.05,9.02 141.89,9.02 141.51,8.64 141.51,7.62 141.38,7.49 ; 3 cut-outs
V_3P3_A on BOTTOM: 133.13,56.13 133.13,56.77 133.42,57.06 133.42,62.55 133.46,62.59 133.46,62.81 134.02,63.37 137.7,63.37 138.08,63.75 138.08,64.14 139.35,65.41 141.89,65.41 142.65,66.17 143.16,66.17 143.29,66.04 143.29,65.66 143.16,65.53 143.16,64.77 143.04,64.64 141.51,64.64 141.38,64.52 141.38,63.63 141.51,63.5 142.15,63.5 142.4,63.25 142.4,60.71 141.36,59.66 141.36,57.84 141.26,57.73 140.39,57.73 140.29,57.84 140.29,59.61 141,60.33 141,62.48 140.88,62.61 140.37,62.61 140.24,62.74 140.24,63.5 140.11,63.63 139.35,63.63 139.1,63.37 139.1,63.25 138.59,62.74 138.46,62.74 138.08,62.36 137.32,62.36 137.19,62.23 137.19,61.59 137.07,61.47 136.56,61.47 136.43,61.59 136.43,62.1 136.3,62.23 134.4,62.23 134.27,62.1 134.27,56.52 133.89,56.13 ; 3 cut-outs
V_3P3_LAN on BOTTOM: 41.56,7.24 41.31,7.49 41.31,10.79 41.18,10.92 39.28,10.92 39.02,11.18 39.02,11.3 38.64,11.68 38.64,12.32 38.77,12.45 39.15,12.45 39.28,12.32 39.28,11.81 39.4,11.68 41.56,11.68 43.09,10.16 43.09,7.75 42.58,7.24
V_3P3_LAN on L3: 36.86,18.41 38.77,18.41 39.02,18.16 39.02,17.65 38.77,17.4 37.37,17.4 36.36,16.38 36.36,13.72 34.7,12.06 34.7,11.18 35.97,9.91 37.37,9.91 38.18,10.72 38.62,10.72 39.02,11.13 39.02,11.56 39.15,11.68 40.29,11.68 40.42,11.56 40.42,10.54 38.51,8.64 35.72,8.64 33.31,11.05 33.31,12.19 35.34,14.22 35.34,16.89
V_3P3_PCIVAUX on TOP: 117.51,222.38 117.51,223.39 117.76,223.65 125.51,223.65 125.76,223.39 125.76,222.76 125.64,222.63 123.22,222.63 122.97,222.38 ; 4 cut-outs
V_3P3_PCIVAUX on TOP: 144.81,198.88 144.56,199.14 144.56,199.9 143.04,201.42 141.13,201.42 139.1,203.45 127.54,203.45 126.65,204.34 117.89,204.34 117.51,204.72 117.51,205.49 117.64,205.61 123.73,205.61 126.14,208.03 141.51,208.03 144.11,205.42 146.02,205.42 148.5,202.95 148.5,199.14 148.24,198.88 ; 4 cut-outs
V_3P3_PCIVAUX on BOTTOM: 145.58,198.88 145.45,199.01 145.45,201.17 145.58,201.29 150.02,201.29 150.15,201.17 150.15,199.14 149.89,198.88
V_5_CODEC on TOP: 164.7,81.66 164.57,81.79 164.57,83.06 164.32,83.31 164.32,86.49 164.45,86.61 165.21,86.61 165.34,86.49 165.34,85.72 165.84,85.22 165.84,81.79 165.72,81.66
V_5_LCD1 on BOTTOM: 38.77,111 38.51,111.25 38.51,113.67 38.64,113.79 40.17,113.79 40.29,113.67 40.29,111.12 40.17,111
V_5_LCD2 on BOTTOM: 41.31,111.63 41.18,111.76 41.18,113.54 40.29,114.43 38.64,114.43 38.64,115.82 39.02,116.2 39.4,116.2 40.24,117.04 41.16,117.04 41.74,116.46 41.82,116.46 42.2,116.08 42.2,111.76 42.07,111.63 ; 1 cut-out
V_5HDD on TOP: 14.51,191.52 14,192.02 14,192.53 12.86,193.68 10.96,193.68 10.57,194.06 10.57,200.91 10.96,201.29 16.8,201.29 17.05,201.04 17.05,198.37 16.16,197.49 16.16,195.33 16.54,194.94 16.54,193.42 17.05,192.91 18.32,192.91 18.45,192.79 18.45,191.64 18.32,191.52 ; 4 cut-outs
V_5P0_A on TOP: 162.85,87.12 162.72,87.25 162.72,88.77 162.85,88.9 164.24,88.9 165.26,87.88 165.26,87.25 165.13,87.12 ; 1 cut-out
V_5P0_A on TOP: 128.18,3.3 128.05,3.43 128.05,5.08 127.8,5.33 127.8,7.49 129.95,7.49 130.72,6.73 139.48,6.73 139.86,7.11 139.86,14.35 140.62,15.11 144.69,15.11 145.45,14.35 145.45,3.81 144.94,3.3 ; 2 cut-outs
V_5P0_A on BOTTOM: 125.13,2.29 124.87,2.54 124.87,6.6 125.38,7.11 125.38,9.91 128.18,9.91 128.68,9.4 128.68,8 129.07,7.62 131.48,7.62 132.37,6.73 135.29,6.73 135.54,6.48 135.54,3.43 134.4,2.29
V_5P0_A on BOTTOM: 145.45,5.59 145.32,5.71 145.32,7.11 145.27,7.16 144.89,7.16 144.69,7.37 144.69,8.51 144.94,8.76 146.46,8.76 146.59,8.64 146.59,5.84 146.34,5.59 ; 1 cut-out
V_5P0_HDMI_CONN on BOTTOM: 117,38.73 116.49,39.24 115.73,39.24 115.48,39.5 115.48,40.89 114.97,41.4 114.97,42.8 115.1,42.93 116.75,42.93 118.4,41.27 118.4,38.99 118.14,38.73 ; 2 cut-outs
V_19_INV on TOP: 39.66,31.24 39.53,31.37 39.53,38.23 40.17,38.86 41.82,38.86 43.47,40.51 45.25,40.51 45.37,40.39 45.37,39.37 44.99,38.99 44.99,31.88 44.36,31.24
VGA_CORE on TOP: 104.55,83.06 103.92,83.69 103.92,95.12 104.55,95.76 114.97,95.76 115.35,95.38 115.35,89.53 113.95,88.14 113.95,83.31 113.7,83.06
VGA_CORE on TOP: 83.24,95.48 83.24,95.61 81.46,97.39 81.46,97.9 81.97,98.4 81.97,98.79 81.46,99.29 81.46,99.8 81.97,100.31 81.97,100.56 81.46,101.07 81.46,101.71 81.97,102.21 81.97,102.47 81.84,102.6 81.84,102.85 81.97,102.98 82.35,102.98 82.86,102.47 82.86,102.21 82.23,101.58 82.23,101.07 82.86,100.44 82.86,100.31 82.23,99.67 82.23,99.42 82.35,99.29 82.35,99.17 82.86,98.66 82.86,98.53 83.11,98.28 83.5,98.28 83.62,98.4 83.62,98.4 83.75,98.53 83.75,98.91 83.24,99.42 83.24,99.67 83.75,100.18 83.75,100.69 83.24,101.2 83.24,101.45 83.75,101.96 83.75,103.23 84.26,103.74 85.4,103.74 85.65,103.48 85.65,103.23 85.02,102.6 85.02,102.34 86.16,101.2 86.16,99.42 86.67,98.91 86.67,98.28 86.16,97.77 87.31,96.63 87.31,95.99 87.05,95.74 86.67,95.74 85.78,96.63 85.02,96.63 83.88,95.48
VGA_CORE on TOP: 79.56,95.36 79.43,95.48 79.43,95.61 79.94,96.12 79.94,96.75 79.81,96.88 79.3,96.88 79.18,97.01 79.18,99.42 79.43,99.67 79.43,100.31 79.3,100.44 79.3,103.48 79.43,103.61 79.69,103.61 80.83,102.47 80.83,102.21 80.29,101.68 80.29,101.22 80.7,100.82 80.7,100.18 80.32,99.8 80.32,99.17 80.78,98.71 80.78,98.23 80.32,97.77 80.32,97.26 80.83,96.75 80.83,96.25 79.94,95.36
VGA_CORE on BOTTOM: 79.94,95.61 79.81,95.74 79.81,97.52 79.43,97.9 79.43,99.29 79.3,99.29 78.8,99.8 78.8,102.34 79.69,103.23 80.07,103.23 80.45,102.85 81.59,102.85 81.65,102.79 81.72,102.85 82.35,102.85 82.48,102.72 82.48,98.91 82.35,98.79 82.1,98.79 81.59,98.28 81.59,97.77 81.46,97.64 81.08,97.64 80.7,97.26 80.7,97.03 80.96,96.78 80.96,96.37 80.83,96.25 80.55,96.25 80.45,96.14 80.45,95.74 80.32,95.61 ; 8 cut-outs
VGA_CORE on BOTTOM: 80.45,108.33 80.35,108.43 80.35,110.16 80.53,110.34 83.24,110.34 83.6,109.98 84.74,109.98 85.63,109.09 85.63,108.84 85.5,108.71 85.12,108.71 84.74,109.09 83.32,109.09 82.56,108.33 ; 4 cut-outs
VGA_CORE on BOTTOM: 85.38,93.34 85.25,93.47 85.25,94.61 85.05,94.82 84.23,94.82 84.08,94.67 83.19,94.67 83.12,94.74 83.12,95.63 82.86,95.89 82.86,96.5 83.5,97.13 83.5,100.56 83.75,100.82 83.75,102.98 84,103.23 85.15,103.23 85.53,102.85 85.53,102.47 86.04,101.96 86.04,101.2 86.26,100.97 86.26,100.56 86.19,100.49 85.6,100.49 85.53,100.56 85.53,101.07 85.4,101.2 84.64,101.2 84.51,101.07 84.51,100.56 84.69,100.39 85.07,100.39 85.15,100.31 85.15,99.55 85.27,99.42 86.16,99.42 86.8,98.79 86.8,98.4 86.42,98.02 86.42,97.39 86.67,97.13 86.67,96.68 87.2,96.14 87.2,95.91 87.1,95.81 86.26,95.81 86.14,95.69 86.14,93.47 86.01,93.34 ; 14 cut-outs
VGA_CORE on L3: 79.79,107.95 81.19,109.35 84.23,109.35 84.25,109.33 85.36,109.33 85.53,109.17 85.53,108.76 85.22,108.46 85.22,108.36 86.01,107.57 93.63,107.57 102.52,98.68 114.08,98.68 115.48,97.28 115.48,89.66 113.95,88.14 113.95,83.31 113.7,83.06 102.01,83.06 100.36,84.71 99.16,84.71 95.79,88.07 93.31,88.07 92.36,89.03 89.7,89.03 84.11,94.61 80.42,94.61 79.79,95.25
VGA_CORE on L4: 79.79,98.93 79.79,107.95 82.2,110.36 92.74,110.36 93.63,109.47 93.63,107.57 102.52,98.68 113.95,98.68 115.35,97.28 115.35,89.53 113.95,88.14 113.95,83.31 113.7,83.06 102.01,83.06 101,84.07 100.74,84.07 94.52,90.3 93.51,90.3 92.36,89.15 89.57,89.15
VOUT_INV on TOP: 29.8,37.34 29.29,37.85 27.59,37.85 27.59,39.5 31.66,39.5 31.78,39.37 31.78,37.59 31.53,37.34
VOUT_INV on BOTTOM: 32.55,35.81 32.29,36.07 27.34,36.07 27.34,42.42 31.78,42.42 31.78,39.12 33.05,37.85 34.7,37.85 34.83,37.72 34.83,35.81

Small or netless copper shapes (teardrops, artwork), in the pictures only: 5 on TOP, 5 on BOTTOM, 1 on L5GND

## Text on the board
Ref Des/Silkscreen Bottom: F15:1.5A/6V | F2:2A/6V | F5:2A/6V | F7:1.5A/6V
Ref Des/Silkscreen Top: 1-2:ME DISABLE | SERVICE | MODE | EMPTY:NORMAL(DEFAULT) | 1-2.CLR_CMOS | RTCRST | EMPTY(DEFAULT) | 1-2:NORMAL(DEFAULT) | PSWD | EMPTY:CLEAR PASSWORD | JO1121 | FAN_CPU | SATA ODD | SATAP1 | SATA HDD | CONVERTER | TOUCH | X4:25MHZ | LVDS | X9503:24MHZ | CHARGER | RJ1 | LOUT1 | CPU1 | X9505:27MHZ | USB4 | HDMI OUT | NGFF_WIFI | HDMI IN | Dell PN:3YHRW | WWW.DELL.COM | Rev:A00 | SD3 | SSUSB1 | UHS1 | PWRCN1 | X9502:14.31818MHZ | DCIN1 | F16:3A/32V | USB3 | F17:2A/6V | F14:2A/6V | X9504:32.768KHZ | DIMM1 | BATTERY | WEBCAM | DIMM2 | For DDR3L Only | F1:1.5A/6V | SPEAKER | F3:1.5A/6V | SSUSB2 | Skylake-U | 14091-1 | 3YHRW | M2xL2.5 | MADE IN TAIWAN
User.33: ByImpedance:100.0@_REF_L1=("3.5/10.0(L1)")|_REF_L6=("3.5/10.0(L6)")|Type="DP"|_REF_L4=("4.0/9.0(L4)")|_REF_L3=("4.0/9.0(L3)")|imp="100.0" | ByImpedance:110.0@_REF_L1=("nil(L1)")|_REF_L6=("nil(L6)")|Type="DP"|_REF_L4=("3.5/13.0(L4)")|_REF_L3=("3.5/13.0(L3)")|imp="110.0" | ByImpedance:27.4@_REF_L1=("12.0(L1)")|_REF_L6=("12.0(L6)")|Type="SE"|_REF_L4=("16.0(L4)")|_REF_L3=("16.0(L3)")|imp="27.4" | ByImpedance:33.0@_REF_L1=("9.0(L1)")|_REF_L6=("9.0(L6)")|Type="SE"|_REF_L4=("12.0(L4)")|_REF_L3=("12.0(L3)")|imp="33.0" | ByImpedance:34.0@_REF_L1=("8.5(L1)")|_REF_L6=("8.5(L6)")|Type="SE"|_REF_L4=("11.5(L4)")|_REF_L3=("11.5(L3)")|imp="34.0" | ByImpedance:35.0@_REF_L1=("8.0(L1)")|_REF_L6=("8.0(L6)")|Type="SE"|_REF_L4=("10.5(L4)")|_REF_L3=("10.5(L3)")|imp="35.0" | ByImpedance:37.5@_REF_L1=("7.0(L1)")|_REF_L6=("7.0(L6)")|Type="SE"|_REF_L4=("9.5(L4)")|_REF_L3=("9.5(L3)")|imp="37.5" | ByImpedance:39.0@_REF_L1=("6.5(L1)")|_REF_L6=("6.5(L6)")|Type="SE"|_REF_L4=("9.0(L4)")|_REF_L3=("9.0(L3)")|imp="39.0" | ByImpedance:40.0@_REF_L1=("6.5(L1)")|_REF_L6=("6.5(L6)")|Type="SE"|_REF_L4=("8.5(L4)")|_REF_L3=("8.5(L3)")|imp="40.0" | ByImpedance:42.0@_REF_L1=("5.5(L1)")|_REF_L6=("5.5(L6)")|Type="SE"|_REF_L4=("7.5(L4)")|_REF_L3=("7.5(L3)")|imp="42.0" | ByImpedance:45.0@_REF_L1=("5.0(L1)")|_REF_L6=("5.0(L6)")|Type="SE"|_REF_L4=("6.5(L4)")|_REF_L3=("6.5(L3)")|imp="45.0" | ByImpedance:48.0@_REF_L1=("4.5(L1)")|_REF_L6=("4.5(L6)")|Type="SE"|_REF_L4=("5.5(L4)")|_REF_L3=("5.5(L3)")|imp="48.0" | ByImpedance:50.0@_REF_L1=("4.0(L1)")|_REF_L6=("4.0(L6)")|Type="SE"|_REF_L4=("5.0(L4)")|_REF_L3=("5.0(L3)")|imp="50.0" | ByImpedance:52.0@_REF_L1=("3.5(L1)")|_REF_L6=("3.5(L6)")|Type="SE"|_REF_L4=("4.5(L4)")|_REF_L3=("4.5(L3)")|imp="52.0" | ByImpedance:55.0@_REF_L1=("nil(L1)")|_REF_L6=("nil(L6)")|Type="SE"|_REF_L4=("4.0(L4)")|_REF_L3=("4.0(L3)")|imp="55.0" | ByImpedance:65.0@_REF_L1=("8.0/6.0(L1)")|_REF_L6=("8.0/6.0(L6)")|Type="DP"|_REF_L4=("9.0/5.0(L4)")|_REF_L3=("9.0/5.0(L3)")|imp="65.0" | ByImpedance:68.0@_REF_L1=("6.5/4.0(L1)")|_REF_L6=("6.5/4.0(L6)")|Type="DP"|_REF_L4=("7.5/4.0(L4)")|_REF_L3=("7.5/4.0(L3)")|imp="68.0" | ByImpedance:70.0@_REF_L1=("7.0/6.0(L1)")|_REF_L6=("7.0/6.0(L6)")|Type="DP"|_REF_L4=("8.0/6.0(L4)")|_REF_L3=("8.0/6.0(L3)")|imp="70.0" | ByImpedance:72.0@_REF_L1=("7.0/8.0(L1)")|_REF_L6=("7.0/8.0(L6)")|Type="DP"|_REF_L4=("7.0/5.0(L4)")|_REF_L3=("7.0/5.0(L3)")|imp="72.0" | ByImpedance:75.0@_REF_L1=("6.0/6.0(L1)")|_REF_L6=("6.0/6.0(L6)")|Type="DP"|_REF_L4=("7.0/6.0(L4)")|_REF_L3=("7.0/6.0(L3)")|imp="75.0" | ByImpedance:80.0@_REF_L1=("5.0/5.0(L1)")|_REF_L6=("5.0/5.0(L6)")|Type="DP"|_REF_L4=("6.0/6.0(L4)")|_REF_L3=("6.0/6.0(L3)")|imp="80.0" | ByImpedance:85.0@_REF_L1=("5.0/8.0(L1)" "4.0/4.5(L1)")|_REF_L6=("5.0/8.0(L6)" "4.0/4.5(L6)")|Type="DP"|_REF_L4=("5.0/5.5(L4)")|_REF_L3=("5.0/5.5(L3)")|imp="85.0" | ByImpedance:90.0@_REF_L1=("4.0/6.0(L1)")|_REF_L6=("4.0/6.0(L6)")|Type="DP"|_REF_L4=("5.0/8.0(L4)" "4.0/5.0(L4)")|_REF_L3=("5.0/8.0(L3)" "4.0/5.0(L3)")|imp="90.0" | ByImpedance:93.0@_REF_L1=("4.0/8.0(L1)" "3.5/5.5(L1)")|_REF_L6=("4.0/8.0(L6)" "3.5/5.5(L6)")|Type="DP"|_REF_L4=("5.0/9.0(L4)" "4.0/5.5(L4)")|_REF_L3=("5.0/9.0(L3)" "4.0/5.5(L3)")|imp="93.0" | ByImpedance:95.0@_REF_L1=("4.0/10.0(L1)" "3.5/6.0(L1)")|_REF_L6=("4.0/10.0(L6)" "3.5/6.0(L6)")|Type="DP"|_REF_L4=("4.0/6.5(L4)")|_REF_L3=("4.0/6.5(L3)")|imp="95.0" | LayerIndex:nil | Source:6-1.2-7c.xls | artWorks:("_REF_L3" "_REF_L4" "_REF_L6" "_REF_L1") | gtImpOutlineUsed:BOARD GEOMETRY/PANEL_OUTLINE
User.34: Board Accuracy Check,Jun 05 11:21:29 2015,Passed | Dummy-Static-No Shape On Layer Check,Jun 05 11:21:30 2015,Passed | Split Plane Check,Dec 24 16:24:54 2014,Passed
User.35: GND | 1V_VCCSA | VCC_CORE | 1V_VCCGT
User.36: AGND | GND
User.39: This gerber is just for your reference to find the DP impedance traces in layer L1. | DP IMPEDANCE TABLE: L1 | * - Denotes that WIDTH | is NOT used in this layer | inside board outline. | IMP(Ohm) | 65.0 | 68.0 | 70.0 | 72.0 | 75.0 | 80.0 | 85.0 | 90.0 | 93.0 | 95.0 | 100.0 | 110.0 | WIDTH(mils) | *8.0/6.0 | *6.5/4.0 | *7.0/6.0 | *7.0/8.0 | *6.0/6.0 | 5.0/5.0 | *5.0/8.0 | 4.0/4.5 | 4.0/6.0 | *4.0/8.0 | *3.5/5.5 | *4.0/10.0 | *3.5/6.0 | 3.5/10.0 | *nil | TYPE | DP
User.41: This gerber is just for your reference to find the SE impedance traces in layer L1. | SE IMPEDANCE TABLE: L1 | * - Denotes that WIDTH | is NOT used in this layer | inside board outline. | IMP(Ohm) | 27.4 | 33.0 | 34.0 | 35.0 | 37.5 | 39.0 | 40.0 | 42.0 | 45.0 | 48.0 | 50.0 | 52.0 | 55.0 | WIDTH(mils) | *12.0 | *9.0 | *8.5 | *8.0 | *7.0 | *6.5 | 6.5 | *5.5 | *5.0 | *4.5 | 4.0 | *3.5 | *nil | TYPE | SE
User.43: This gerber is just for your reference to find the DP impedance traces in layer L3. | DP IMPEDANCE TABLE: L3 | * - Denotes that WIDTH | is NOT used in this layer | inside board outline. | IMP(Ohm) | 65.0 | 68.0 | 70.0 | 72.0 | 75.0 | 80.0 | 85.0 | 90.0 | 93.0 | 95.0 | 100.0 | 110.0 | WIDTH(mils) | *9.0/5.0 | *7.5/4.0 | *8.0/6.0 | *7.0/5.0 | *7.0/6.0 | 6.0/6.0 | 5.0/5.5 | *5.0/8.0 | *4.0/5.0 | *5.0/9.0 | *4.0/5.5 | *4.0/6.5 | 4.0/9.0 | *3.5/13.0 | TYPE | DP
User.45: Note:Refer to DRILL layer for ELLIPSE drill direction | FIGURE | SIZE | 10.0 | 12.0 | 16.0 | 20.0 | 28.0 | 30.0 | 36.0 | 37.0 | 39.0 | 40.0 | 60.0 | 91.0 | 109.0 | 158.0 | 42.0 | 44.0 | 50.0 | 54.0 | 63.0 | 67.0 | 86.0 | 138.0 | 178.0 | 48.0x16.0 | 56.0x24.0 | 60.0x24.0 | 60.0x28.0 | 67.0x28.0 | 67.0x30.0 | 67.0x32.0 | 91.0x28.0 | 156.0x32.0 | 166.0x32.0 | 197.0x178.0 | DRILL CHART: TOP to BOTTOM | ALL UNITS ARE IN MILS | PLATED | NON-PLATED | QTY | 1631 | 2321 | 1025 | 40 | 18 | 14 | 8 | 32 | 11 | 4 | 1 | 5 | 3 | 2 | This gerber is just for your reference to find the DP impedance traces in layer L4. | This gerber is just for your reference to find the DP impedance traces in layer L6. | This gerber is just for your reference to find the SE impedance traces in layer L3. | This gerber is just for your reference to find the SE impedance traces in layer L4. | This gerber is just for your reference to find the SE impedance traces in layer L6. | DP IMPEDANCE TABLE: L4 | DP IMPEDANCE TABLE: L6 | SE IMPEDANCE TABLE: L3 | SE IMPEDANCE TABLE: L4 | SE IMPEDANCE TABLE: L6 | * - Denotes that WIDTH | is NOT used in this layer | inside board outline. | Model | Skylake-U | PCB_NO | 14091 | VER. | Layer | DRILL | L1 | L2GND | L3 | TMASK | TPLACE | TSILK | TSMD | Designer | AKIM | Date | 07/13/2015 | IMP(Ohm) | 27.4 | 65.0 | 33.0 | 68.0 | 34.0 | 70.0 | 35.0 | 72.0 | 37.5 | 75.0 | 80.0 | 85.0 | 90.0 | 45.0 | 48.0 | 93.0 | 52.0 | 95.0 | 100.0 | 55.0 | 110.0 | WIDTH(mils) | *12.0 | *16.0 | *9.0 | *11.5 | *8.5 | *10.5 | *8.0 | *7.0 | *9.5 | *6.5 | 6.5 | 8.5 | *5.5 | *7.5 | *5.0 | *4.5 | 4.0 | 5.0 | *3.5 | *4.0 | *nil | *8.0/6.0 | *9.0/5.0 | *6.5/4.0 | *7.5/4.0 | *7.0/6.0 | *7.0/5.0 | *7.0/8.0 | *6.0/6.0 | 5.0/5.0 | 6.0/6.0 | *5.0/8.0 | 5.0/5.5 | 4.0/4.5 | *4.0/5.0 | *4.0/6.0 | *4.0/8.0 | *5.0/9.0 | *3.5/5.5 | *4.0/5.5 | *4.0/10.0 | *4.0/6.5 | *3.5/6.0 | *4.0/9.0 | *3.5/13.0 | 3.5/10.0 | TYPE | SE | DP | BMASK | BPLACE | BSILK | BSMD | L4 | L5GND | L6
